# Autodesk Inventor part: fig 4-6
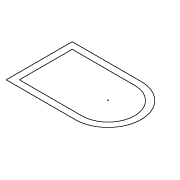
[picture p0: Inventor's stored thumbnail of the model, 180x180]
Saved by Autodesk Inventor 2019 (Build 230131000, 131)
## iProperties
Created: 2005-02
Part Number: fig 4-6
Document SubType Name: Modeling
Designer: CADCIM
Manufacturer: Standard
Standards Organization: Custom
Density: 1 g/cm^3
Material: Generic
Appearance: Default
Author: CADCIM
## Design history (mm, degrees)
sketch "Sketch1"
  geometry: L1 (12.963, 23.563)-(-25.99, 23.563); L2 (-25.99, 23.563)-(-25.99, -13.729); L3 (-25.99, -13.729)-(12.963, -13.729); L4 (-22.275, 19.848)-(12.963, 19.848); L5 (12.963, -10.014)-(-22.275, -10.014); L6 (-22.275, -10.014)-(-22.275, 19.848); A1 r 18.646 centre (12.963, 4.917) between (12.963, -13.729) and (12.963, 23.563); A2 r 14.931 centre (12.963, 4.917) between (12.963, -10.014) and (12.963, 19.848)
  constraints: 12 end point, 4 point on circle, 2 centre point, 2 parallel, 2 perpendicular, 2 tangent, 1 horizontal, 4 other
